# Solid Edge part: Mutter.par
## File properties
Sűrűség: 0,000 kg/m^3
Pontosság: 0,990
Author: bmolnar
Last saved by: psaghy
Revision: 77
Username: bmolnar
Dokumentum tartalom típus: 0
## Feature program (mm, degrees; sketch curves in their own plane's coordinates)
base feature "unnamed BaseFeature 1"
sketch for "Furat_1" plane through (8, 0, 0) normal (1, 0, 0) x-axis (0, 1, 0)
  hole centre (0, 0) bore radius 7.188
hole "Furat_1" through  StartChamferOffset = 0.47 mm; StartChamferAngle = 45 deg
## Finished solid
Body 1: solid body, 23 faces, 47 edges, 26 vertices.
  Faces by surface: cone 14, plane 8, cylinder 1
  Edges by curve: spline 24, circle 16, line 7
Bounding box of the edges (mm): 8.000 x 27.713 x 24.000, from (0, -13.8564, -12) to (8, 13.8564, 12).
Cylindrical faces by radius (mm): R7.188 x1
Conical faces (half-angle, radius in mm at the cone's reference point): 45 deg R7.658 x1, 60 deg R7.5939 x1, 60 deg R12.9282 x12
Planar faces by outward normal: +x 1, +z 1, -x 1, -z 1, oblique 4
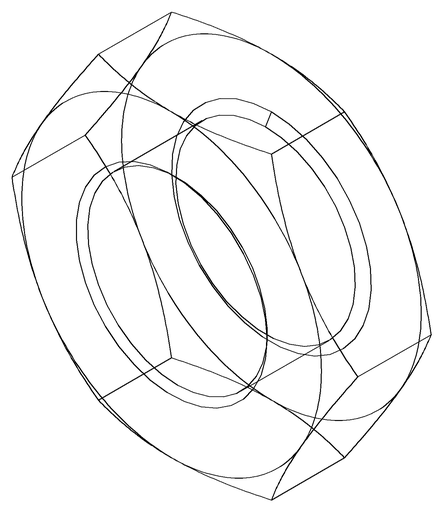
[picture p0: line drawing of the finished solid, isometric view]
